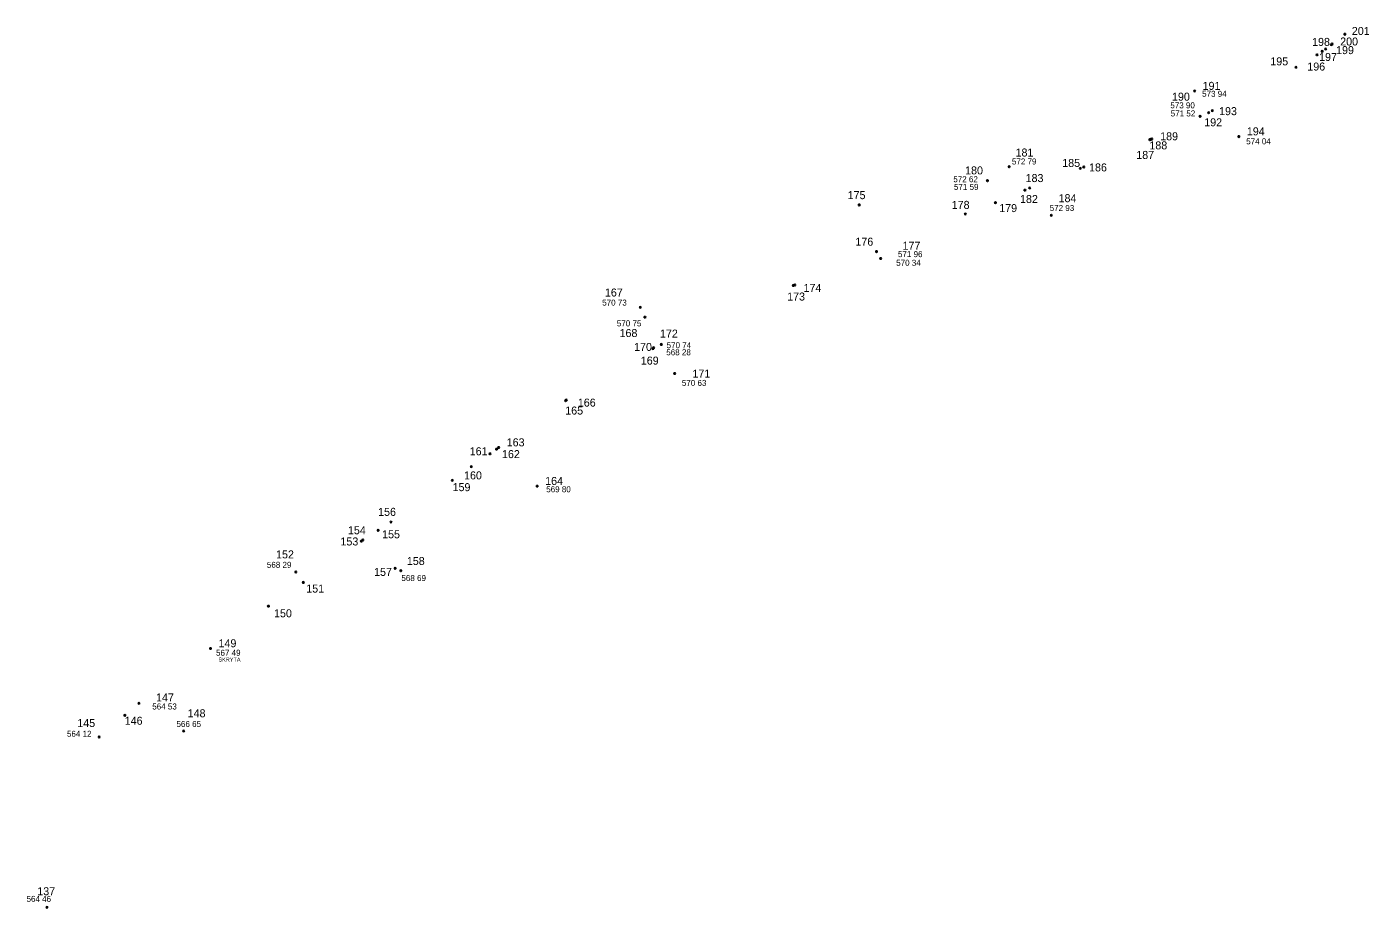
# Model space of a CAD drawing. Extents: x -710806 to -710046, y -1116918 to -1116046.
# Drawn here: x -710292.5 to -710124.8, y -1116372.5 to -1116262.3 of the extents above; entities that cross this region are included whole.
import ezdxf
from ezdxf.enums import TextEntityAlignment as Align

# ---------------------------------------------------------------- set-up
doc = ezdxf.new("R2010")
doc.units = 0
doc.header["$LTSCALE"] = 0.4
doc.header["$PDMODE"] = 32
doc.header["$PDSIZE"] = 0.2
for name, color, linetype in [('43', 7, 'Continuous'), ('55', 7, 'Continuous'), ('56', 7, 'Continuous')]:
    doc.layers.add(name, color=color, linetype=linetype)
doc.layers.add('63', color=7, linetype='Continuous', lineweight=13)

msp = doc.modelspace()

# ---------------------------------------------------------------- linework, layer by layer
at = {"layer": '56'}
for p in [(-710129.482, -1116264.517), (-710129.371, -1116264.446), (-710127.793, -1116263.212), (-710131.257, -1116265.793), (-710130.614, -1116265.352), (-710130.184, -1116265.058), (-710133.903, -1116267.344), (-710146.564, -1116270.318), (-710144.807, -1116273.029), (-710144.35, -1116272.773), (-710145.874, -1116273.486), (-710152.029, -1116276.353), (-710151.908, -1116276.314), (-710141.032, -1116276.007), (-710152.157, -1116276.4), (-710169.737, -1116279.784), (-710160.852, -1116279.989), (-710160.411, -1116279.808), (-710172.446, -1116281.529), (-710167.771, -1116282.706), (-710167.178, -1116282.427), (-710188.469, -1116284.549), (-710171.446, -1116284.268), (-710175.202, -1116285.691), (-710164.463, -1116285.845), (-710186.313, -1116290.382), (-710185.783, -1116291.255), (-710196.702, -1116294.627), (-710196.521, -1116294.565), (-710215.816, -1116297.369), (-710215.252, -1116298.589), (-710214.232, -1116302.528), (-710214.165, -1116302.39), (-710213.195, -1116302), (-710211.533, -1116305.63), (-710225.163, -1116309.033), (-710225.068, -1116308.938), (-710233.521, -1116314.886), (-710234.617, -1116315.667), (-710233.795, -1116315.087), (-710236.934, -1116317.266), (-710239.325, -1116318.997), (-710228.712, -1116319.715), (-710246.967, -1116324.204), (-710250.675, -1116326.594), (-710250.495, -1116326.452), (-710248.58, -1116325.241), (-710246.458, -1116329.99), (-710258.873, -1116330.447), (-710245.746, -1116330.286), (-710257.927, -1116331.755), (-710262.291, -1116334.718), (-710269.531, -1116340.009), (-710280.233, -1116348.37), (-710278.467, -1116346.858), (-710283.445, -1116351.066), (-710272.881, -1116350.323), (-710289.962, -1116372.375)]:
    msp.add_point(p, dxfattribs=at)

# ---------------------------------------------------------------- texts
at = {"layer": '43'}
for s, p in [('573 94 ', (-710143.9502, -1116271.036)), ('573 90 ', (-710147.9212, -1116272.477)), ('574 04 ', (-710138.4382, -1116276.977)), ('572 79 ', (-710167.7182, -1116279.497)), ('572 62 ', (-710175.0402, -1116281.714)), ('572 93 ', (-710162.9962, -1116285.31)), ('571 96 ', (-710181.9592, -1116291.082)), ('570 73 ', (-710218.9142, -1116297.139)), ('570 75 ', (-710217.0852, -1116299.738)), ('570 74 ', (-710210.8652, -1116302.465)), ('570 63 ', (-710208.9582, -1116307.182)), ('569 80 ', (-710225.9072, -1116320.478)), ('568 29 ', (-710260.8132, -1116329.926)), ('568 69 ', (-710244.0022, -1116331.578)), ('567 49 ', (-710267.1712, -1116340.918)), ('564 53 ', (-710275.1372, -1116347.635)), ('566 65 ', (-710272.1112, -1116349.826)), ('564 12 ', (-710285.7972, -1116351.048)), ('564 46 ', (-710290.8492, -1116371.688))]:
    msp.add_text(s, height=0.75, dxfattribs=at).set_placement(p, align=Align.CENTER)
for s, p in [('571 52', (-710149.547, -1116273.492)), ('571 59', (-710176.633, -1116282.675)), ('570 34', (-710183.85, -1116292.164)), ('568 28', (-710212.58, -1116303.354))]:
    msp.add_text(s, height=0.75, dxfattribs=at).set_placement(p)
at = {"layer": '55'}
for s, p in [('201', (-710126.916, -1116263.304)), ('198', (-710131.88, -1116264.674)), ('200', (-710128.371, -1116264.622)), ('195', (-710137.102, -1116267.105)), ('197', (-710131.007, -1116266.557)), ('199', (-710128.884, -1116265.701)), ('196', (-710132.479, -1116267.755)), ('191', (-710145.564, -1116270.168)), ('190', (-710149.385, -1116271.521)), ('193', (-710143.503, -1116273.33)), ('192', (-710145.356, -1116274.727)), ('189', (-710150.864, -1116276.474)), ('194', (-710140.032, -1116275.857)), ('181', (-710168.935, -1116278.503)), ('187', (-710153.852, -1116278.806)), ('188', (-710152.213, -1116277.611)), ('185', (-710163.103, -1116279.808)), ('186', (-710159.75, -1116280.367)), ('180', (-710175.237, -1116280.737)), ('183', (-710167.679, -1116281.697)), ('175', (-710189.918, -1116283.833)), ('178', (-710176.913, -1116285.049)), ('179', (-710170.978, -1116285.45)), ('182', (-710168.377, -1116284.316)), ('184', (-710163.559, -1116284.211)), ('176', (-710188.949, -1116289.65)), ('177', (-710183.06, -1116290.153)), ('174', (-710195.43, -1116295.431)), ('167', (-710220.249, -1116296.004)), ('173', (-710197.477, -1116296.508)), ('168', (-710218.42, -1116301.074)), ('172', (-710213.367, -1116301.14)), ('170', (-710216.602, -1116302.807)), ('169', (-710215.765, -1116304.517)), ('171', (-710209.308, -1116306.143)), ('165', (-710225.206, -1116310.764)), ('166', (-710223.634, -1116309.769)), ('161', (-710237.144, -1116315.853)), ('163', (-710232.521, -1116314.736)), ('162', (-710233.108, -1116316.209)), ('160', (-710237.848, -1116318.866)), ('159', (-710239.285, -1116320.339)), ('164', (-710227.712, -1116319.565)), ('156', (-710248.589, -1116323.428)), ('154', (-710252.36, -1116325.727)), ('153', (-710253.294, -1116327.128)), ('155', (-710248.086, -1116326.23)), ('152', (-710261.341, -1116328.745)), ('157', (-710249.092, -1116330.936)), ('158', (-710244.997, -1116329.571)), ('151', (-710257.569, -1116333.019)), ('150', (-710261.592, -1116336.109)), ('149', (-710268.531, -1116339.859)), ('147', (-710276.338, -1116346.634)), ('148', (-710272.387, -1116348.609)), ('145', (-710286.18, -1116349.831)), ('146', (-710280.253, -1116349.543)), ('137', (-710291.179, -1116370.859))]:
    msp.add_text(s, height=1, dxfattribs=at).set_placement(p)
at = {"layer": '63'}
msp.add_text('SKRYTA', height=0.5, dxfattribs=at).set_placement((-710268.543, -1116341.641))

doc.saveas('drawing.dxf')
